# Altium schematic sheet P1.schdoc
size 420 x 297 mm; Symbol: Sheet-Symbol_A4; Company: 嘉立创EDA; Version: V1.0; Page Size: A4; @Project Name: 电子负载(简易板); @Page Count: 1; @Update Date: 2026-04-01; @Create Date: 2026-04-01; @Schematic Name: Schematic1; @Page No: 1; @Page Name: P1; Device: Sheet-Symbol_A4; Border: 1; Title Block Position: 3; Width: 1655; Height: 1170; Region Start: 1; X Region Count: 6; Y Region Count: 4; Blade Width: 10; @Board Name: Board1; @Create Time: 13:57:11; @Update Time: 13:57:11
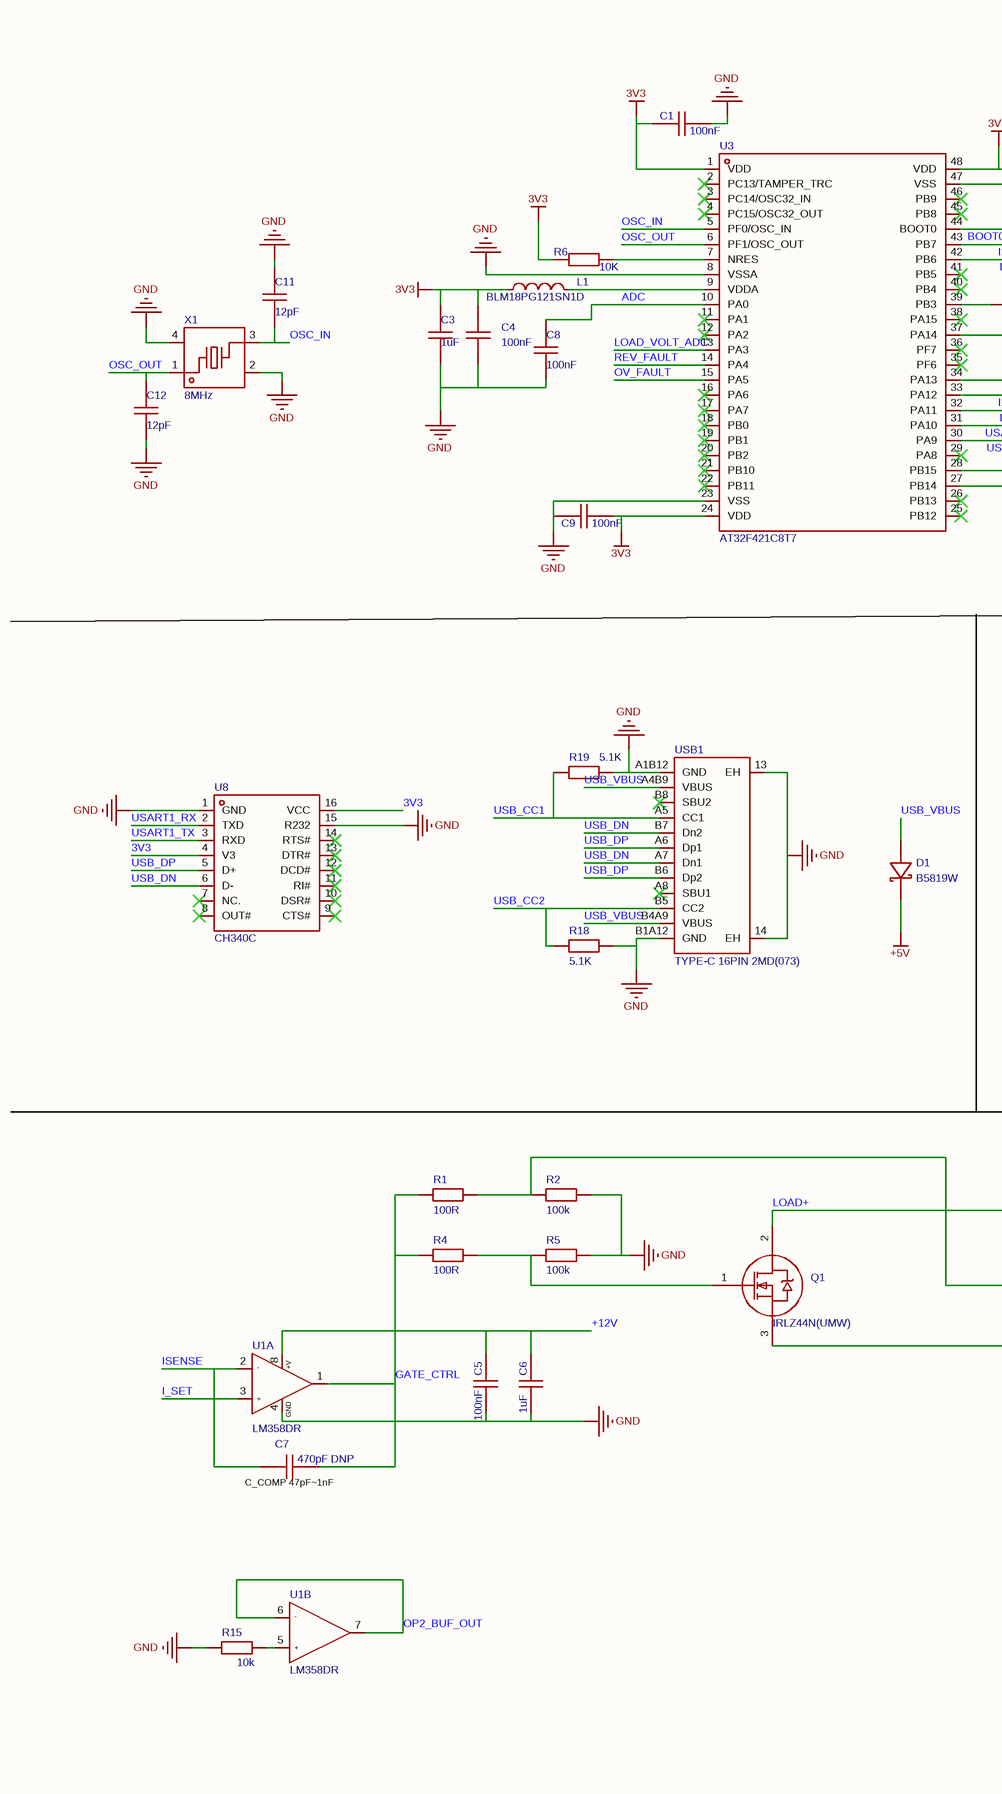
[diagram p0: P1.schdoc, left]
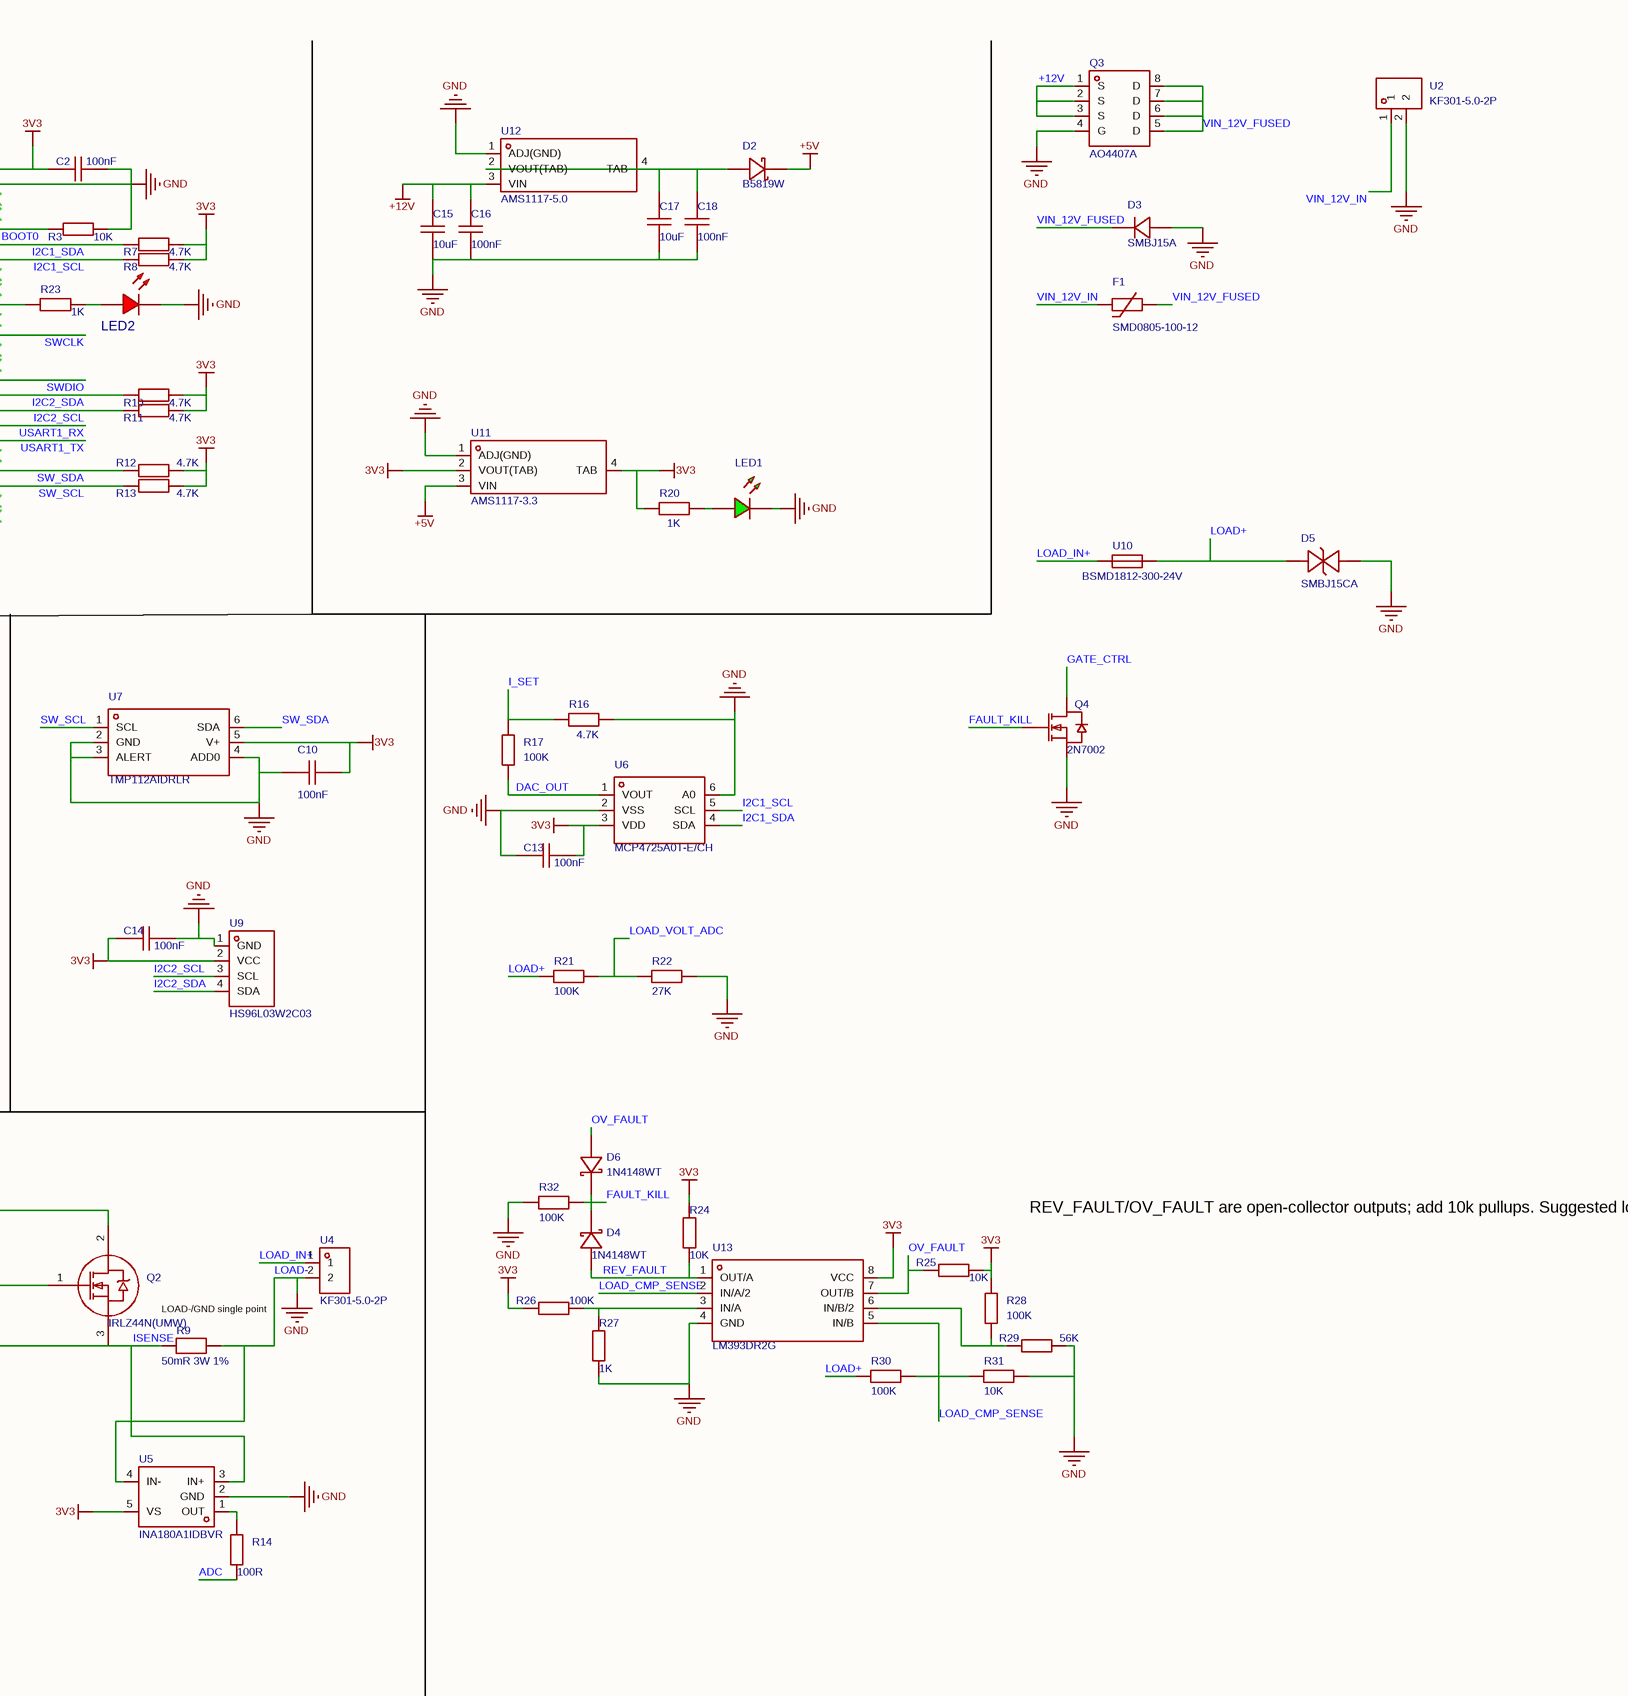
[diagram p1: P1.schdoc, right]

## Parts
C1  100nF  [C0603]
C2  100nF  [C0603]
C3  1uF  [C0603]
C4  100nF  [C0603]
C5  100nF  [C0603]
C6  1uF  [C0603]
C7  470pF DNP  [C0603]
C8  100nF  [C0603]
C9  100nF  [C0603]
C10  100nF  [C0603]
C11  12pF  [C0603]
C12  12pF  [C0603]
C13  100nF  [C0603]
C14  100nF  [C0603]
C15  10uF  [C0603]
C16  100nF  [C0603]
C17  10uF  [C0603]
C18  100nF  [C0603]
D1  B5819W  [SOD-123F_L2.7-W1.6-LS3.8-RD-1]
D2  B5819W  [SOD-123F_L2.7-W1.6-LS3.8-RD-1]
D3  SMBJ15A  [SMB_L4.3-W3.6-LS5.3-RD]
D4  1N4148WT  [SOD-523_L1.2-W0.8-LS1.6-FD]
D5  SMBJ15CA  [SMB_L4.6-W3.6-LS5.4-BI]
D6  1N4148WT  [SOD-523_L1.2-W0.8-LS1.6-FD]
F1  SMD0805-100-12  [R0805]
L1  BLM18PG121SN1D  [L0603]
LED1  (no value)  [LED_0603]
LED2  (no value)  [LED_0603]
Q1  IRLZ44N(UMW)  [TO-220-3_L10.2-W4.5-P2.54-L]
Q2  IRLZ44N(UMW)  [TO-220-3_L10.2-W4.5-P2.54-L]
Q3  AO4407A  [SOP-8_L5.0-W4.0-P1.27-LS6.0-BL]
Q4  2N7002  [SOT-23-3_L2.9-W1.3-P1.90-LS2.4-BR]
R1  100R  [R0603]
R2  100k  [R0603]
R3  10K  [R0603]
R4  100R  [R0603]
R5  100k  [R0603]
R6  10K  [R0603]
R7  4.7K  [R0603]
R8  4.7K  [R0603]
R9  50mR 3W 1%  [RES-SMD_L6.4-W3.2-R2512]
R10  4.7K  [R0603]
R11  4.7K  [R0603]
R12  4.7K  [R0603]
R13  4.7K  [R0603]
R14  100R  [R0603]
R15  10k  [R0603]
R16  4.7K  [R0603]
R17  100K  [R0603]
R18  5.1K  [R0603]
R19  5.1K  [R0603]
R20  1K  [R0603]
R21  100K  [R0603]
R22  27K  [R0603]
R23  1K  [R0603]
R24  10K  [R0603]
R25  10K  [R0603]
R26  100K  [R0603]
R27  1K  [R0603]
R28  100K  [R0603]
R29  56K  [R0603]
R30  100K  [R0603]
R31  10K  [R0603]
R32  100K  [R0603]
U1  LM358DR  [SOIC-8_L5.0-W4.0-P1.27-LS6.0-BL]  (parts A,B of 2)
U2  KF301-5.0-2P  [CONN-TH_P5.00_KF301-5.0-2P]
U3  AT32F421C8T7  [LQFP-48_L7.0-W7.0-P0.50-LS9.0-BL]
U4  KF301-5.0-2P  [CONN-TH_P5.00_KF301-5.0-2P]
U5  INA180A1IDBVR  [SOT-23-5_L3.0-W1.7-P0.95-LS2.8-BR]
U6  MCP4725A0T-E/CH  [SOT-23-6_L2.9-W1.6-P0.95-LS2.8-BL]
U7  TMP112AIDRLR  [SOT-563_L1.6-W1.2-P0.50-LS1.6-BR]
U8  CH340C  [SOP-16_L10.0-W3.9-P1.27-LS6.0-BL]
U9  HS96L03W2C03  [OLED-TH_L27.8-W27.2-P2.54_C9900033791]
U10  BSMD1812-300-24V  [F1812]
U11  AMS1117-3.3  [SOT-223-4_L6.5-W3.5-P2.30-LS7.0-BR]
U12  AMS1117-5.0  [SOT-223_L6.7-W3.5-P2.30-BR]
U13  LM393DR2G  [SOIC-8_L5.0-W4.0-P1.27-LS6.0-BL]
USB1  TYPE-C 16PIN 2MD(073)  [USB-C-SMD_TYPE-C-16PIN-2MD-073]
X1  8MHz  [CRYSTAL-SMD_4P-L3.2-W2.5-BL-1]

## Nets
3V3: C1.1 C2.1 C3.2 C4.2 C9.1 C10.2 C13.2 C14.1 L1.1 R6.1 R7.2 R8.2 R10.2 R11.2 R12.2 R13.2 R20.1 R24.2 R25.2 R26.1 R28.2 U3.1(VDD) U3.24(VDD) U3.48(VDD) U5.5(VS) U6.3(VDD) U7.5(V+) U8.4(V3) U8.16(VCC) U9.2(VCC) U11.2(VOUT(TAB)) U11.4(TAB) U13.8(VCC)
+5V: D1.1(K) D2.1(K) U11.3(VIN)
+12V: C5.2 C6.2 C15.2 C16.2 Q3.1(S) Q3.2(S) Q3.3(S) U1.8(+V) U12.3(VIN)
LOAD-: C1.2 C2.2 C3.1 C4.1 C5.1 C6.1 C8.1 C9.2 C10.1 C11.2 C12.1 C13.1 C14.2 C15.1 C16.1 C17.1 C18.1 D3.2(A) D5.2 LED1.1(C) LED2.1(C) Q3.4(G) Q4.2(S) R2.2 R3.2 R5.2 R9.2 R15.1 R16.2 R18.1 R19.1 R22.2 R27.1 R29.2 R31.2 R32.1 U1.4(GND) U2.2 U3.8(VSSA) U3.23(VSS) U3.47(VSS) U4.2 U5.2(GND) U5.4(IN-) U6.2(VSS) U6.6(A0) U7.2(GND) U7.3(ALERT) U7.4(ADD0) U8.1(GND) U8.15(R232) U9.1(GND) U11.1(ADJ(GND)) U12.1(ADJ(GND)) U13.4(GND) USB1.13(EH) USB1.14(EH) USB1.A1B12(GND) USB1.B1A12(GND) X1.2(GND) X1.4(GND)  [also labelled GND]
ADC: C8.2 R14.1 U3.10(PA0)
BOOT0: R3.1 U3.44(BOOT0)
DAC_OUT: R17.1 U6.1(VOUT)
FAULT_KILL: D4.2(K) D6.2(K) Q4.1(G) R32.2
GATE_CTRL: C7.2 Q4.3(D) R1.1 R4.1 U1.1(OUT1)
I2C1_SCL: R8.1 U3.42(PB6) U6.5(SCL)
I2C1_SDA: R7.1 U3.43(PB7) U6.4(SDA)
I2C2_SCL: R11.1 U3.32(PA11) U9.3(SCL)
I2C2_SDA: R10.1 U3.33(PA12) U9.4(SDA)
I_SET: R16.1 R17.2 U1.3(+IN1)
ISENSE: C7.1 Q1.3(S) Q2.3(S) R9.1 U1.2(-IN1) U5.3(IN+)
LOAD+: D5.1 Q1.2(D) Q2.2(D) R21.1 R30.1 U10.2
LOAD_CMP_SENSE: R30.2 R31.1 U13.2(IN/A/2) U13.5(IN/B)
LOAD_IN+: U4.1 U10.1
LOAD_VOLT_ADC: R21.2 R22.1 U3.13(PA3)
OP2_BUF_OUT: U1.6(-IN2) U1.7(OUT2)
OSC_IN: C11.1 U3.5(PF0/OSC_IN) X1.3
OSC_OUT: C12.2 U3.6(PF1/OSC_OUT) X1.1
OV_FAULT: D6.1(A) R25.1 U3.15(PA5) U13.7(OUT/B)
REV_FAULT: D4.1(A) R24.1 U3.14(PA4) U13.1(OUT/A)
SW_SCL: R13.1 U3.27(PB14) U7.1(SCL)
SW_SDA: R12.1 U3.28(PB15) U7.6(SDA)
SWCLK: U3.37(PA14)
SWDIO: U3.34(PA13)
USART1_RX: U3.31(PA10) U8.2(TXD)
USART1_TX: U3.30(PA9) U8.3(RXD)
USB_CC1: R19.2 USB1.A5(CC1)
USB_CC2: R18.2 USB1.B5(CC2)
USB_DN: U8.6(D-) USB1.A7(Dn1) USB1.B7(Dn2)
USB_DP: U8.5(D+) USB1.A6(Dp1) USB1.B6(Dp2)
USB_VBUS: D1.2(A) USB1.A4B9(VBUS) USB1.B4A9(VBUS)
VIN_12V_FUSED: D3.1(K) F1.2 Q3.5(D) Q3.6(D) Q3.7(D) Q3.8(D)
VIN_12V_IN: F1.1 U2.1
NetC17_2: C17.2 C18.2 D2.2(A) U12.2(VOUT(TAB)) U12.4(TAB)
NetL1_2: L1.2 U3.9(VDDA)
NetLED1_2: LED1.2(A) R20.2
NetLED2_2: LED2.2(A) R23.2
NetQ1_1: Q1.1(G) R4.2 R5.1
NetQ2_1: Q2.1(G) R1.2 R2.1
NetR6_2: R6.2 U3.7(NRES)
NetR14_2: R14.2 U5.1(OUT)
NetR15_2: R15.2 U1.5(+IN2)
NetR23_1: R23.1 U3.39(PB3)
NetR26_2: R26.2 R27.2 U13.3(IN/A)
NetR28_1: R28.1 R29.1 U13.6(IN/B/2)

Not connected (* = marked no-connect by the designer): U3 2(PC13/TAMPER_TRC)* 3(PC14/OSC32_IN)* 4(PC15/OSC32_OUT)* 11(PA1)* 12(PA2)* 16(PA6)* 17(PA7)* 18(PB0)* 19(PB1)* 20(PB2)* 21(PB10)* 22(PB11)* 25(PB12)* 26(PB13)* 29(PA8)* 35(PF6)* 36(PF7)* 38(PA15)* 40(PB4)* 41(PB5)* 45(PB8)* 46(PB9)*; U8 7(NC.)* 8(OUT#)* 9(CTS#)* 10(DSR#)* 11(RI#)* 12(DCD#)* 13(DTR#)* 14(RTS#)*; USB1 A8(SBU1)* B8(SBU2)*

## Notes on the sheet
- REV_FAULT/OV_FAULT are open-collector outputs; add 10k pullups. Suggested logic: LOW = FAULT if used directly.
- (near R9) LOAD-/GND single point
- (near C7) C_COMP 47pF
  nF

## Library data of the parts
C1-C4 C8-C10 C13-C18 = CAP_0603: Symbol: Capacitance; 3D Model: ac125912035d415993ca9572d50418b10819f05c4eef4c71ace90d822a990e87; 3D Model Transform: 62.992,31.496,0,0,0,0,0,0,0; ConvertToPcb: yes; ModelName: C0603_L1.6-W0.8-H0.8
C5 = CAP_0603: LM358 +12V local decoupling; Symbol: Capacitance; 3D Model: ac125912035d415993ca9572d50418b10819f05c4eef4c71ace90d822a990e87; 3D Model Transform: 62.992,31.496,0,0,0,0,0,0,0; Add into BOM: yes; ModelName: C0603_L1.6-W0.8-H0.8
C6 = CAP_0603: LM358 +12V bulk decoupling; Symbol: Capacitance; 3D Model: ac125912035d415993ca9572d50418b10819f05c4eef4c71ace90d822a990e87; 3D Model Transform: 62.992,31.496,0,0,0,0,0,0,0; Add into BOM: yes; ModelName: C0603_L1.6-W0.8-H0.8
C7 = CAP_0603: Loop compensation GATE_CTRL to ISENSE; tune 47pF-1nF; Symbol: Capacitance; 3D Model: ac125912035d415993ca9572d50418b10819f05c4eef4c71ace90d822a990e87; 3D Model Transform: 62.992,31.496,0,0,0,0,0,0,0; Add into BOM: yes; ModelName: C0603_L1.6-W0.8-H0.8
C11 C12 = CAP_0603: Symbol: Capacitance; 3D Model: ac125912035d415993ca9572d50418b10819f05c4eef4c71ace90d822a990e87; 3D Model Transform: 62.992,31.496,0,0,0,0,0,0,0; Add into BOM: yes; ModelName: C0603_L1.6-W0.8-H0.8
D1 D2 = B5819W: 二极管配置:-;正向压降(Vf):580mV@1A;直流反向耐压(Vr):40V;平均整流电流(Io):1A;; Manufacturer: GOODWORK(固得沃克); Symbol: B5819W_C2943878; 3D Model: 71f0e82389b44cdcbce37efe700504dc; 3D Model Transform: 147.6375,62.992,0,0,0,0,-0.002,0.005,0; Reverse Voltage (Vr): 40V; Average Rectified Current (Io): 1A; Reverse Leakage Current (Ir): 50uA@40V; AddInBom: yes
D3 = SMBJ15A_C19077569: 极性:单向;反向截止电压(Vrwm):15V;钳位电压:24.4V;峰值脉冲电流(Ipp):24.59A@10/1000us;峰值脉冲功率(Ppp):600W@10/1000us;击穿电压:18.5V;; Manufacturer: R+O(宏嘉诚); AddInBom: yes; ModelId: c889f7f4bb1d4007adeb7906fc7ccf080819f05c4eef4c71ace90d822a990e87; ModelName: SMB_L4.32-W3.62-LS5.3-RD; ModelTransform: 208.661,142.5194,0,0,0,0,0,0,0; Polarity: 单向; Reverse Stand-Off Voltage (Vrwm): 15V; Clamping Voltage: 24.4V; Voltage - Breakdown: 18.5V; Reverse Leakage Current (Ir): 5uA; level of protection: IEC 61000-4-2; Type: TVS
D4 D6 = 1N4148WT_C7420320: 二极管配置:独立式;整流电流:150mA;直流反向耐压(Vr):100V;正向压降(Vf):1.25V@150mA;反向恢复时间(Trr):4ns;; Manufacturer: R+O(宏嘉诚); AddInBom: yes; ModelId: 8f56a03db567494d8f4c9d12aa52a7410819f05c4eef4c71ace90d822a990e87; ModelName: SOD-523_L1.2-W0.8-H0.7-LS1.6; ModelTransform: 62.992,31.496,0,0,0,0,0,0,0; Diode Configuration: 独立式; Pd - Power Dissipation: 150mW; Current - Rectified: 150mA; Voltage - DC Reverse(Vr): 100V; Non-Repetitive Peak Forward Surge Current: 2A; Reverse Leakage Current (Ir): 1uA@75V; Reverse Recovery Time (trr): 4ns; Operating Junction Temperature Range: -55℃~+150℃
D5 = SMBJ15CA_C19077570: 极性:双向;反向截止电压(Vrwm):15V;钳位电压:24.4V;峰值脉冲电流(Ipp):24.59A@10/1000us;峰值脉冲功率(Ppp):600W@10/1000us;击穿电压:18.5V;; Manufacturer: R+O(宏嘉诚); AddInBom: yes; ModelId: 56a671846d664f15ac0751d5510bb56a0819f05c4eef4c71ace90d822a990e87; ModelTransform: 212.598,142.5194,0,0,0,0,0,0,0; Polarity: 双向; Reverse Stand-Off Voltage (Vrwm): 15V; Clamping Voltage: 24.4V; Voltage - Breakdown: 18.5V; Reverse Leakage Current (Ir): 5uA; level of protection: IEC 61000-4-2; Type: TVS
F1 = SMD0805-100-12: 耐压(Vmax):12V;最大电流(Imax):40A;保持电流(Ihold):1A;跳闸电流(Itrip):2A;; Manufacturer: R+O(宏嘉诚); AddInBom: yes; ModelId: 37a81e68749a4138bd2dfa6897b24b850819f05c4eef4c71ace90d822a990e87; ModelName: R0805_L2.0-W1.3-H0.6; ModelTransform: 78.74,51.181,0,0,0,0,0,-0.0005,0; Voltage - Max: 12V; Current - Max: 40A; Hold Current: 1A; Trip Current: 2A; Power Dissipation: 600mW; Resistance - Initial (Ri) (Min): 40mΩ; Resistance - Post Trip (R1) (Max): 270mΩ; Time to Trip(Max): 300ms
L1 = BLM18PG121SN1D: 阻抗@频率:120Ω@100MHz;误差:±25%;直流电阻(DCR):50mΩ;; Manufacturer: muRata(村田); Symbol: BLM18PG121SN1D_C14709; AddInBom: yes; ModelId: 2bc5ec593d464d6ba9807aec0b5673c20819f05c4eef4c71ace90d822a990e87; ModelName: L0603_L1.6-W0.8-H0.5_BEAD; ModelTransform: 62.992,31.496,0,180,0,0,0.094,0.629,0; Tolerance: ±25%; DC Resistance(DCR): 50mΩ; Current Rating: 2A; Number of Circuits: 1
LED1 = LED_0603-G: Symbol: LED_G_OLD; Convert to PCB: yes; 3D Model: 8b5fcaf0229049f8a37a9c352bb0ca0a0819f05c4eef4c71ace90d822a990e87; 3D Model Transform: 63.1,31.6,23.7,0,0,0,0,0,0; ModelName: LED-0603_G
LED2 = LED_0603-R: Symbol: LED_R; Convert to PCB: yes; 3D Model: dd8257b0d61a4cd7b68939a056e080950819f05c4eef4c71ace90d822a990e87; 3D Model Transform: 58.72,29.4,22.03,0,0,0,0,0,0; ModelName: LED-0603_R
Q1 Q2 = IRLZ44N(UMW): 数量:1个N沟道;漏源电压(Vdss):55V;连续漏极电流(Id):47A;导通电阻(RDS(on)):22mΩ@10V;耗散功率(Pd):110W;阈值电压(Vgs(th)):2V@250uA;; Manufacturer: UMW(友台半导体); AddInBom: yes; ModelId: 0d00e432dfb443ffb7502e153b1219100819f05c4eef4c71ace90d822a990e87; ModelTransform: 395.2748,167.716,0,0,0,0,-0.591,5.316,-137.795; Number: 1个N沟道; Drain to Source Voltage: 55V; Current - Continuous Drain(Id): 47A; Pd - Power Dissipation: 110W; Gate Charge(Qg): 48nC; Input Capacitance(Ciss): 1.7nF; Reverse Transfer Capacitance (Crss@Vds): 150pF; Type: N沟道; Output Capacitance(Coss): 400pF
Q3 = AO4407A_C2841482: 数量:1个P沟道;漏源电压(Vdss):30V;连续漏极电流(Id):14A;导通电阻(RDS(on)):9.5mΩ@10V；14.7mΩ@4.5V;耗散功率(Pd):3.1W;阈值电压(Vgs(th)):1.8V@250uA;; Manufacturer: UMW(友台半导体); AddInBom: yes; ModelId: a3315c1c78f949e6bb82c6eaca1c53c70819f05c4eef4c71ace90d822a990e87; ModelName: SOP-8_L5.0-W4.0-H1.8-LS6.2-P1.27; ModelTransform: 244.094,196.85,0,90,0,0,0,0,0; Number: 1个P沟道; Drain to Source Voltage: 30V; Current - Continuous Drain(Id): 14A; Pd - Power Dissipation: 3.1W; Gate Charge(Qg): 40nC@10V；20nC@4.5V; Input Capacitance(Ciss): 2.05nF; Reverse Transfer Capacitance (Crss@Vds): 300pF; Output Capacitance(Coss): 330pF
Q4 = 2N7002_C7420321: 数量:1个N沟道;漏源电压(Vdss):60V;连续漏极电流(Id):115mA;导通电阻(RDS(on)):900mΩ@10V;耗散功率(Pd):225mW;阈值电压(Vgs(th)):1.6V@250uA;; Manufacturer: R+O(宏嘉诚); AddInBom: yes; ModelId: c62791f0466c4ae2a892c056b845b0ca0819f05c4eef4c71ace90d822a990e87; ModelName: SOT-23-3P_L2.9-W1.3-H1.0-LS2.4-P0.95; ModelTransform: 98.425,114.173,0,180,0,0,0.0005,-0.0005,0; Number: 1个N沟道; Drain to Source Voltage: 60V; Current - Continuous Drain(Id): 115mA; Pd - Power Dissipation: 225mW; Gate Charge(Qg): 1.6nC@10V; Input Capacitance(Ciss): 50pF; Reverse Transfer Capacitance (Crss@Vds): 5pF; Type: N沟道; Output Capacitance(Coss): 25pF
R1 = Res_0603: Q2 gate resistor; Symbol: 电阻; Add into BOM: yes; ModelId: fc143cca1e79419f9cd78b61e9279f080819f05c4eef4c71ace90d822a990e87; ModelTransform: 31.8897,63.7794,0,90,0,0,0,0,0
R2 = Res_0603: Q2 gate pulldown; Symbol: 电阻; Add into BOM: yes; ModelId: fc143cca1e79419f9cd78b61e9279f080819f05c4eef4c71ace90d822a990e87; ModelTransform: 31.8897,63.7794,0,90,0,0,0,0,0
R3 R6-R8 R10-R14 R16-R19 = Res_0603: Symbol: 电阻; ConvertToPcb: yes; ModelId: fc143cca1e79419f9cd78b61e9279f080819f05c4eef4c71ace90d822a990e87; ModelTransform: 31.8897,63.7794,0,90,0,0,0,0,0
R4 = Res_0603: Q1 gate resistor; Symbol: 电阻; Add into BOM: yes; ModelId: fc143cca1e79419f9cd78b61e9279f080819f05c4eef4c71ace90d822a990e87; ModelTransform: 31.8897,63.7794,0,90,0,0,0,0,0
R5 = Res_0603: Q1 gate pulldown; Symbol: 电阻; Add into BOM: yes; ModelId: fc143cca1e79419f9cd78b61e9279f080819f05c4eef4c71ace90d822a990e87; ModelTransform: 31.8897,63.7794,0,90,0,0,0,0,0
R9 = HoJLR2512-3W-50mR-1%: Low-side current sense resistor; Manufacturer: Milliohm(毫欧); Add into BOM: yes; ModelId: 3c946b39f1b547de9af067cb1ede82cc0819f05c4eef4c71ace90d822a990e87; ModelTransform: 252.7554,126.7714,0,0,0,0,0,0,0
R15 = Res_0603: U4.2 +IN pulldown; Symbol: 电阻; Add into BOM: yes; ModelId: fc143cca1e79419f9cd78b61e9279f080819f05c4eef4c71ace90d822a990e87; ModelTransform: 31.8897,63.7794,0,90,0,0,0,0,0
R20-R32 = Res_0603: Symbol: 电阻; 3D Model: fc143cca1e79419f9cd78b61e9279f080819f05c4eef4c71ace90d822a990e87; 3D Model Transform: 31.8897,63.7794,0,90,0,0,0,0,0; ConvertToPcb: yes
U1 = LM358DR: 放大器数:2;轨到轨:-;增益带宽积(GBW):700kHz;输入失调电压(Vos):3mV;压摆率(SR):300V/ms;输入偏置电流(Ib):20nA;; Manufacturer: TI(德州仪器); Relevance: []; AddInBom: yes; ModelId: 7abc64c95a1a4a04a4ef38f9097c870b0819f05c4eef4c71ace90d822a990e87; ModelTransform: 192.913,236.22,0,0,0,0,0,0,0; Number of Channels: 2; Maximum Power Supply Range (Vdd-Vss): 32V; Gain Bandwidth Product: 700kHz; Vos - Input Offset Voltage: 3mV; Input Offset Voltage Drift(Vos TC): 7uV/℃; Ib - Input Bias Current: 20nA; Input Offset Current(Ios): 2nA; Input Voltage Noise Density: 40nV/√Hz@1kHz; Common Mode Rejection Ratio(CMRR): 99dB; Input offset current drift(Ios TC): 10pA/℃; Quiescent Current: 700uA; Output Current: 20mA; Single supply: 3V~32V; Dual Supply: -16V~16V
U2 U4 = KF301-5.0-2P: 结构:1x2P;间距:5mm;颜色:蓝色;安装方式:直插;排数:1;每排PIN数:2;额定电流:17A;额定电压:250V;线规 - AWG:14~22;线规 - 平方毫米:1.5;工作温度:-30℃~+120℃;; Manufacturer: KEFA(科发); AddInBom: yes; ModelId: 442de893d0fc4728b9e5c7abc29ccda50819f05c4eef4c71ace90d822a990e87; ModelTransform: 417.322,299.21594,0,0,0,0,11.811,7.874,-137.795; Number of Positions or Pins: 1x2P; Pitch: 5mm; Number of PINs Per Row: 2; Current Rating: 17A; Voltage Rating (Max): 250V; Wire Gauge - AWG: 14~22; Wire Gauge - mm2: 1.5
U3 = AT32F421C8T7: CPU内核:CM4;程序存储容量:64KB;RAM总容量:16KB;GPIO端口数量:-;工作电压范围:-;CPU最大主频:-;程序存储器类型:FLASH;; Manufacturer: ARTERY(雅特力); AddInBom: yes; ModelId: 093be70396ff421eb2cdb946d5311efc0819f05c4eef4c71ace90d822a990e87; ModelName: LQFP-48_L7.0-W7.0-H1.4-LS9.0-P0.50; ModelTransform: 354.331,354.331,0,0,0,0,0,0,0; CPU Core: CM4; Program Storage Size: 64KB; RAM Size: 16KB; Program Memory Type: FLASH; Internal Oscillator: 有
U5 = INA180A1IDBVR: 放大器数:单路;共模电压:-200mV~26V;增益:20V/V;带宽:350kHz;; Manufacturer: TI(德州仪器); AddInBom: yes; ModelId: 0a2a1b8f50944f73965918ad6e5fe1670819f05c4eef4c71ace90d822a990e87; ModelName: SOT-23-5_L2.9-W1.6-H1.1-LS2.8-P0.95; ModelTransform: 114.173,109.636,0,180,0,0,0,0,0; Number of Channels: 单路; Gain: 20V/V; Bandwidth: 350kHz; Ib - Input Bias Current: 100nA; Vos - Input Offset Voltage: 25uV; Differential Voltage: -26V~26V; Single Supply: 2.7V~5.5V; Quiescent Current: 197uA; Output Current: 8mA; Input Offset Voltage Drift(Vos TC): 1uV/℃; Slew Rate: 2V/us; Common Mode Rejection Ratio (CMRR): 100dB; Noise density(eN): 40nV/√Hz@1kHz
U6 = MCP4725A0T-E/CH: 分辨率(位):12位;接口类型:I2C;工作电压:2.7V~5.5V;稳定时间:6us;积分非线性:2LSB;; Manufacturer: MICROCHIP(美国微芯); AddInBom: yes; ModelId: 18da8f6c14a34920b3e136b5c401a1190819f05c4eef4c71ace90d822a990e87; ModelName: SOT-23-6_L2.9-W1.6-H1.5-LS2.8-P0.95; ModelTransform: 110.236,113.364,0,90,0,0,0.0005,0.0005,0; Resolution(Bits): 12位; Number of Channels: 1; Interface: I2C; Settling Time: 6us; Output Type: 电压-缓冲; Integral non - linearity: 2LSB; Power-On Reset: 内置; Voltage Reference: 外置; Data rate: 3.4MHz；100kHz；400kHz; Quiescent Current (Iq): 210uA
U7 = TMP112AIDRLR: 检测温度:-40℃~+125℃;精度:±0.5℃;接口类型:I2C;; Manufacturer: TI(德州仪器); 3D Model: ae4c13e967cf4f598e77975e9d61b1bf0819f05c4eef4c71ace90d822a990e87; 3D Model Transform: 62.992,62.992,0,180,0,0,-0.002,1.178,0; Tolerance: ±0.5℃; Voltage - Supply: 1.4V~3.6V; Standby Current: 1uA; Interface: I2C; Temperature Conversion Time: 26ms; Temperature Resolution: 13bit; AddInBom: yes; ModelName: SOT-563-6P_L1.6-W1.2-H0.6-LS1.6-P0.50
U8 = CH340C: 应用功能:收发器;USB协议版本:USB 2.0;数据速率:2Mbps;; Manufacturer: WCH(南京沁恒); AddInBom: yes; ModelId: 3361a6792abf4a8f8fbca4f1924a67ee0819f05c4eef4c71ace90d822a990e87; ModelName: SOP-16_L9.9-W3.9-H1.5-LS6.0-P1.27; ModelTransform: 240.39054,393.7,0,90,0,0,0,0,0; Applications Function: 收发器; USB Protocol: USB 2.0; Voltage - Supply: 3.3V；5V; Data Rate: 2Mbps; Current - Supply: 7mA; Supply Current (Iq): 50uA
U9 = HS96L03W2C03: 核心芯片:SSD1315芯片;接口类型:I2C;尺寸(inch):0.96;像素分辨率:128x64;; Manufacturer: HS(汉昇); AddInBom: yes; ModelId: bb65183306db4ca69fb52250be49b00e0819f05c4eef4c71ace90d822a990e87; ModelTransform: 1070.864,1094.486,0,0,0,0,0,-498.424,0; Interface: I2C; Dot Pixels: 128x64; Type of Drive: 无源(PMOLED); Display Range: 21.744x10.864mm; Display Color: 白色; Luminance: 180cd/m2
U10 = BSMD1812-300-24V: 耐压(Vmax):24V;最大电流(Imax):40A;保持电流(Ihold):3A;跳闸电流(Itrip):6A;; Manufacturer: BHFUSE(佰宏); AddInBom: yes; ModelId: bca21e458c564d38b781621ca22e660b0819f05c4eef4c71ace90d822a990e87; ModelName: F1812_L4.5-W3.2-H1.0; ModelTransform: 177.165,125.984,0,0,0,0,0.0005,0,0; Voltage - Max: 24V; Current - Max: 40A; Hold Current: 3A; Trip Current: 6A; Power Dissipation: 1.4W; Resistance - Initial (Ri) (Min): 12mΩ; Resistance - Post Trip (R1) (Max): 60mΩ; Time to Trip(Max): 4s
U11 = AMS1117-3.3_C347222: 输出类型:固定;工作电压:12V;输出电压:3.3V;输出电流:1A;电源纹波抑制比(PSRR):60dB@(120Hz);输出极性:正极;; Manufacturer: UMW(友台半导体); 3D Model: 925194bf9823436183a3e0b978a8d0760819f05c4eef4c71ace90d822a990e87; 3D Model Transform: 279.89794,255.905,0,180,0,0,-0.0005,-0.0005,0; Output Type: 固定; Voltage - Supply: 12V; Output Voltage: 3.3V; Output Current: 1A; Voltage Dropout: 1.3V@(1A); standby current: 5mA; Noise: 0.003%Vout; Output Configuration: 正极; Number of Outputs: 1; AddInBom: yes; ModelName: SOT-223-4P_L6.5-W3.5-H1.6-LS7.0-P2.30
U12 = AMS1117-5.0_C347223: 输出类型:固定;工作电压:18V;输出电压:5V;输出电流:1A;电源纹波抑制比(PSRR):60dB@(120Hz);输出极性:正极;; Manufacturer: UMW(友台半导体); AddInBom: yes; ModelId: 925194bf9823436183a3e0b978a8d0760819f05c4eef4c71ace90d822a990e87; ModelName: SOT-223-4P_L6.5-W3.5-H1.6-LS7.0-P2.30; ModelTransform: 279.89794,255.905,0,180,0,0,0,0,0; Output Type: 固定; Maximum Input Voltage: 18V; Output Voltage: 5V; Output Current: 1A; Dropout Voltage: 1.3V@(1A); Output Polarity: 正极; Number of Outputs: 1
U13 = LM393DR2G: 比较器数:双路;输入失调电压(Vos):5mV;输入偏置电流(Ib):25nA;轨到轨:-;; Manufacturer: onsemi(安森美); AddInBom: yes; ModelId: 7abc64c95a1a4a04a4ef38f9097c870b0819f05c4eef4c71ace90d822a990e87; ModelTransform: 192.913,236.22,0,0,0,0,0,0,0; Number of Channels: 双路; Vos - Input Offset Voltage: 5mV; Ib - Input Bias Current: 25nA; Propagation Delay Time: 300ns; Output Mode: TTL；CMOS; Quiescent Current: 400uA; Maximum Power Supply Range (Vdd-Vss): 36V; Single Supply: 2V~36V; Dual Supply: 1V~18V；-18V~-1V; Input Offset Current(Ios): 5nA; Response Time (tr): 1.3us
USB1 = TYPE-C 16PIN 2MD(073): 连接器类型:Type-C;协议标准:-;公母:母;安装方式:卧贴;触点数量:16P;端口数量:1;额定电流 - 电源:3A;工作温度:-25℃~+85℃;; Manufacturer: SHOU HAN(首韩); AddInBom: yes; ModelId: 3a41b9ec9b654a0fad4d118405ec62900819f05c4eef4c71ace90d822a990e87; ModelName: USB-C-SMD_TYPE-C-6PIN-2MD-073; ModelTransform: 351.9678,298.4246,0,0,0,0,0,-47.244,-35.433; Gender: 母; Number of Contacts: 16P; Number of Ports: 1; Current Rating-Power: 3A; Voltage Rating: 5V; Connect-Disconnect Life: 1万次; Detection color: 黑色
X1 = XL2EL89COI-111YLC-8M: 晶振类型:贴片晶振;频率:8MHz;常温频差:±10ppm;负载电容:12pF;频率稳定度:±20ppm;; Manufacturer: YXC(扬兴晶振); Add into BOM: yes; Normal temperature Frequency Tolerance: ±10ppm; Load Capacitance: 12pF; Frequency Stability: ±20ppm; Equivalent Series Resistance(ESR): 150Ω; 3D Model: 4495b492a02c4f389e505ec8ae3aaf1b; 3D Model Transform: 125.984,98.425,0,0,0,0,0,0,0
